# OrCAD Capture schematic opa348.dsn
size A
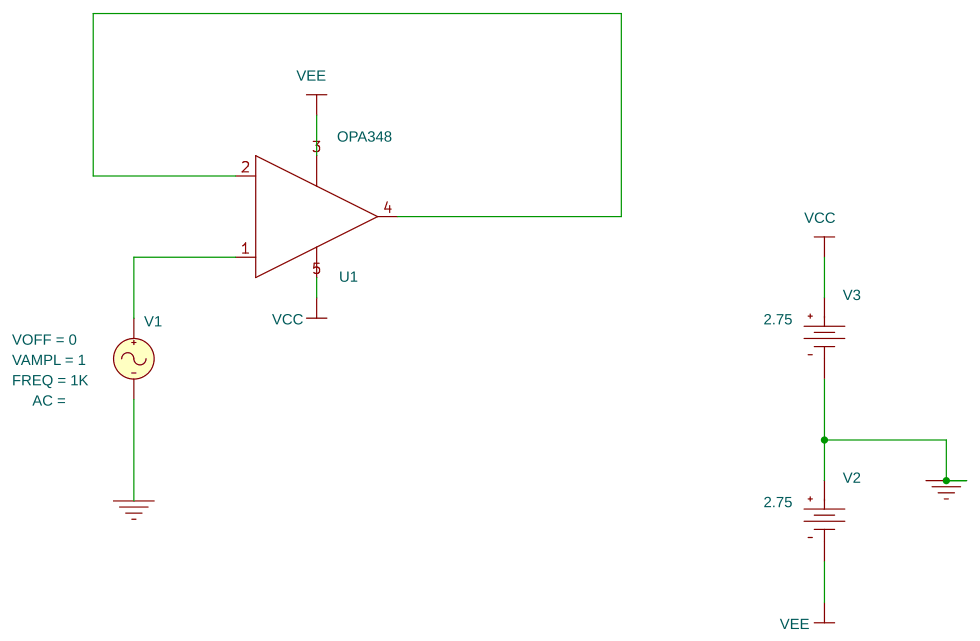
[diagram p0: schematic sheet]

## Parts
U1  OPA348
V1  VSIN
V2  VDC
V3  VDC

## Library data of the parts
U1 = OPA348
V1 = VSIN: FREQ: 1K; VAMPL: 1; VOFF: 0
V2 V3 = VDC: DC: 2.75

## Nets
VCC: U1.5(V+) V3.0(+)
VEE: U1.3(V-) V2.1(-)
0: V1.2(-) V2.0(+) V3.1(-)
N00084: U1.2(-) U1.4(OUT)
N00294: U1.1(+) V1.1(+)
